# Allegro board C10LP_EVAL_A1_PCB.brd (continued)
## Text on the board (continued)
DISPLAY_TOP: FIGURE | SIZE | 8.0 | 10.0 | 12.0 | 13.0 | 28.0 | 35.429 | 39.37 | 40.0 | 43.311 | 44.0 | 62.988 | 125.0 | 118.11 | 127.949 | 75.0x36.0 | 118.11x31.5 | DRILL CHART: TOP to BOTTOM | ALL UNITS ARE IN MILS | TOLERANCE | +3.0/-3.0 | +4.0/-4.0 | PLATED | NON-PLATED | QTY | 262 | 700 | 94 | 9 | 5 | 8 | 32 | 12 | 39 | 1 | 6 | 2 | 4
